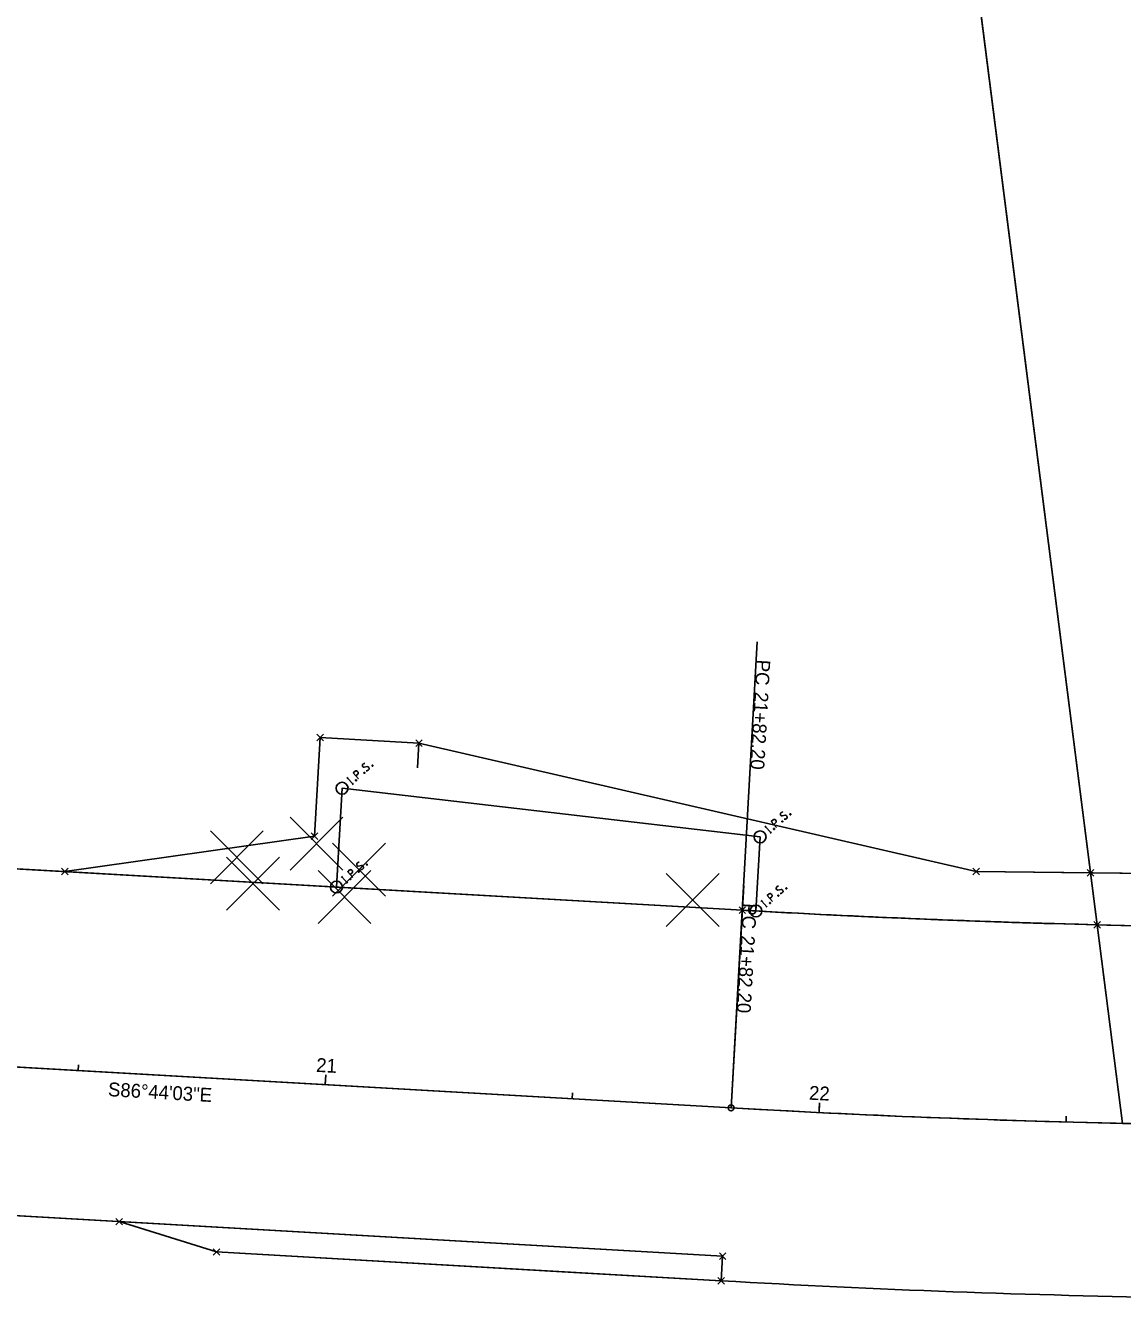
# Model space of a CAD drawing. Extents: x 2273111 to 2279616, y 652916 to 655718.
# Drawn here: x 2274544.8 to 2274766.6, y 654661.8 to 654919.2 of the extents above; entities that cross this region are included whole.
import ezdxf

# ---------------------------------------------------------------- set-up
doc = ezdxf.new("R2010")
doc.units = 0
for name, color, linetype in [('DV_X_Property_Line', 7, 'Continuous'), ('RW_P_Easement_Area', 7, 'Continuous'), ('RW_P_Esmt_SH', 7, 'Continuous'), ('RW_P_Esmt_TMP', 7, 'Continuous'), ('RW_P_Taking_Area', 7, 'Continuous'), ('RW_X_CL', 7, 'Continuous'), ('RW_X_CL_1000_Curve_Data', 7, 'Continuous'), ('RW_X_CL_1000_Stations', 7, 'Continuous'), ('RW_X_CL_100_Curve_Data', 7, 'Continuous'), ('RW_X_CL_100_Stations', 7, 'Continuous'), ('RW_X_CL_500_Stations', 7, 'Continuous'), ('RW_X_Esmt_SH', 7, 'Continuous'), ('SC_Scratch2', 7, 'Continuous'), ('SC_Scratch3', 7, 'Continuous'), ('SC_Scratch4', 7, 'Continuous'), ('SC_Scratch5', 7, 'Continuous'), ('SV_P_Control_Cells_Set', 7, 'Continuous'), ('SV_P_Mon_Cells_Set', 7, 'Continuous'), ('VG_P_Cells', 7, 'Continuous')]:
    doc.layers.add(name, color=color, linetype=linetype)

msp = doc.modelspace()

# ---------------------------------------------------------------- linework, layer by layer
at = {"layer": 'DV_X_Property_Line'}
msp.add_line((2274766.64, 654697.37), (2274705.29, 655177.83), dxfattribs=at)
at = {"layer": 'RW_P_Easement_Area'}
for p, q in [((2274603.77, 654774.71), (2274605.1, 654776.04)), ((2274603.77, 654776.04), (2274605.1, 654774.71)), ((2274603.3, 654755.41), (2274604.43, 654775.37)), ((2274604.43, 654775.37), (2274624.4, 654774.23)), ((2274623.74, 654773.57), (2274625.07, 654774.9)), ((2274623.74, 654774.9), (2274625.07, 654773.57)), ((2274624.4, 654774.23), (2274737.06, 654748.26)), ((2274608.86, 654765.1), (2274607.72, 654745.14)), ((2274693.37, 654755.28), (2274608.86, 654765.1)), ((2274552.81, 654748.27), (2274603.3, 654755.41)), ((2274602.63, 654754.74), (2274603.96, 654756.07)), ((2274602.63, 654756.07), (2274603.96, 654754.74)), ((2274692.53, 654740.3), (2274693.37, 654755.28)), ((2274552.14, 654747.6), (2274553.47, 654748.94)), ((2274552.14, 654748.94), (2274553.47, 654747.6)), ((2274607.72, 654745.14), (2274552.81, 654748.27)), ((2274736.39, 654747.59), (2274737.73, 654748.93)), ((2274736.39, 654748.93), (2274737.73, 654747.59)), ((2274737.06, 654748.26), (2274760.17, 654748.01)), ((2274761.52, 654737.51), (2274760.17, 654748.01)), ((2274760.17, 654748.01), (2274849.53, 654747.02)), ((2274760.17, 654748.01), (2274761.52, 654737.51)), ((2274689.12, 654739.79), (2274690.45, 654741.12)), ((2274689.12, 654741.12), (2274690.45, 654739.79)), ((2274760.85, 654736.84), (2274762.18, 654738.18)), ((2274760.85, 654738.18), (2274762.18, 654736.84)), ((2274563.13, 654676.86), (2274564.46, 654678.2)), ((2274563.13, 654678.2), (2274564.46, 654676.86)), ((2274583.48, 654671.4), (2274563.8, 654677.53)), ((2274563.8, 654677.53), (2274685.8, 654670.57)), ((2274582.81, 654670.73), (2274584.14, 654672.07)), ((2274582.81, 654672.07), (2274584.14, 654670.73)), ((2274685.51, 654665.58), (2274583.48, 654671.4)), ((2274685.13, 654669.9), (2274686.46, 654671.24)), ((2274685.13, 654671.24), (2274686.46, 654669.9)), ((2274685.8, 654670.57), (2274685.51, 654665.58)), ((2274684.85, 654664.91), (2274686.18, 654666.24)), ((2274684.85, 654666.24), (2274686.18, 654664.91))]:
    msp.add_line(p, q, dxfattribs=at)
for start, end in [(266.8043, 268.56091), (268.56091, 270.80398)]:
    msp.add_arc((2274818.07, 656988.81), 2252.01, start, end, dxfattribs=at)
at = {"layer": 'RW_P_Esmt_SH'}
for p, q in [((2274607.72, 654745.14), (2274608.86, 654765.1)), ((2274608.86, 654765.1), (2274693.37, 654755.28)), ((2274693.37, 654755.28), (2274692.53, 654740.3))]:
    msp.add_line(p, q, dxfattribs=at)
at = {"layer": 'RW_P_Esmt_TMP'}
for p, q in [((2274603.3, 654755.41), (2274604.43, 654775.37)), ((2274603.3, 654755.41), (2274604.43, 654775.37)), ((2274604.43, 654775.37), (2274624.4, 654774.23)), ((2274604.43, 654775.37), (2274624.4, 654774.23)), ((2274624.4, 654774.23), (2274624.12, 654769.24)), ((2274624.4, 654774.23), (2274737.06, 654748.26)), ((2274624.4, 654774.23), (2274737.06, 654748.26)), ((2274552.81, 654748.27), (2274603.3, 654755.41)), ((2274552.81, 654748.27), (2274603.3, 654755.41)), ((2274737.06, 654748.26), (2274849.53, 654747.02)), ((2274737.06, 654748.26), (2274849.53, 654747.02)), ((2274563.8, 654677.53), (2274583.48, 654671.4)), ((2274583.48, 654671.4), (2274653.36, 654667.41)), ((2274653.36, 654667.41), (2274678.32, 654665.99)), ((2274678.32, 654665.99), (2274685.51, 654665.58))]:
    msp.add_line(p, q, dxfattribs=at)
at = {"layer": 'RW_P_Taking_Area'}
for p, q in [((2274607.72, 654745.14), (2274608.86, 654765.1)), ((2274608.86, 654765.1), (2274693.37, 654755.28)), ((2274693.37, 654755.28), (2274692.53, 654740.3)), ((2274689.78, 654740.45), (2274607.72, 654745.14))]:
    msp.add_line(p, q, dxfattribs=at)
msp.add_arc((2274818.07, 656988.81), 2252.01, 266.7343, 266.8043, dxfattribs=at)
at = {"layer": 'RW_X_CL'}
msp.add_line((2274458.12, 654713.61), (2274687.5, 654700.52), dxfattribs=at)
msp.add_arc((2274818.07, 656988.81), 2292.01, 266.73428, 271.35095, dxfattribs=at)
at = {"layer": 'RW_X_CL_1000_Stations'}
msp.add_line((2274687.5, 654700.52), (2274690.07, 654745.45), dxfattribs=at)
msp.add_circle((2274687.5, 654700.52), 0.6, dxfattribs=at)
at = {"layer": 'RW_X_CL_100_Stations'}
for p, q in [((2274687.5, 654700.52), (2274692.8, 654794.66)), ((2274555.52, 654708.05), (2274555.59, 654709.25)), ((2274605.44, 654705.2), (2274605.55, 654707.2)), ((2274655.36, 654702.35), (2274655.43, 654703.55)), ((2274705.28, 654699.57), (2274705.38, 654701.57)), ((2274755.24, 654697.66), (2274755.28, 654698.86))]:
    msp.add_line(p, q, dxfattribs=at)
msp.add_circle((2274687.5, 654700.52), 0.6, dxfattribs=at)
at = {"layer": 'RW_X_CL_500_Stations'}
for p, q in [((2274687.5, 654700.52), (2274690.07, 654745.45)), ((2274605.44, 654705.2), (2274605.51, 654706.4)), ((2274705.28, 654699.57), (2274705.34, 654700.77))]:
    msp.add_line(p, q, dxfattribs=at)
msp.add_circle((2274687.5, 654700.52), 0.6, dxfattribs=at)
at = {"layer": 'RW_X_Esmt_SH'}
for p, q in [((2274460.4, 654753.54), (2274689.78, 654740.45)), ((2274456.41, 654683.66), (2274685.8, 654670.57)), ((2274685.8, 654670.57), (2274685.51, 654665.58))]:
    msp.add_line(p, q, dxfattribs=at)
for radius in [2252.01, 2327.01]:
    msp.add_arc((2274818.07, 656988.81), radius, 266.73428, 271.35095, dxfattribs=at)
at = {"layer": 'SC_Scratch2'}
msp.add_lwpolyline([(2274689.78, 654740.45), (2274607.72, 654745.14), (2274608.86, 654765.1), (2274693.37, 654755.28), (2274692.53, 654740.3)], dxfattribs=at)
msp.add_arc((2274818.07, 656988.81), 2252.01, 266.73428, 266.8043, dxfattribs=at)
at = {"layer": 'SC_Scratch3'}
for points in [[(2274692.53, 654740.3), (2274693.37, 654755.28), (2274608.86, 654765.1), (2274607.72, 654745.14), (2274552.81, 654748.27), (2274603.3, 654755.41), (2274604.43, 654775.37), (2274624.4, 654774.23), (2274737.06, 654748.26), (2274760.18, 654748.01), (2274761.52, 654737.51)], [(2274761.52, 654737.51), (2274760.18, 654748.01), (2274849.53, 654747.02), (2274849.67, 654737.02)]]:
    msp.add_lwpolyline(points, dxfattribs=at)
msp.add_lwpolyline([(2274685.8, 654670.57), (2274685.51, 654665.58), (2274583.48, 654671.4), (2274563.8, 654677.53)], close=True, dxfattribs=at)
for start, end in [(266.8043, 268.56095), (268.56095, 270.80398)]:
    msp.add_arc((2274818.07, 656988.81), 2252.01, start, end, dxfattribs=at)
at = {"layer": 'SC_Scratch4'}
for p, q in [((2274761.52, 654737.51), (2274766.64, 654697.37)), ((2274766.64, 654697.37), (2274761.52, 654737.51)), ((2274687.5, 654700.52), (2274458.12, 654713.61))]:
    msp.add_line(p, q, dxfattribs=at)
for points in [[(2274459.83, 654743.56), (2274460.4, 654753.54), (2274689.78, 654740.45)], [(2274687.5, 654700.52), (2274458.12, 654713.61), (2274439.66, 654744.86)], [(2274456.41, 654683.66), (2274685.8, 654670.57), (2274685.51, 654665.58)]]:
    msp.add_lwpolyline(points, dxfattribs=at)
for radius, start, end in [(2252.01, 266.73428, 268.56095), (2252.01, 268.56095, 270.80398), (2292.01, 266.73428, 271.35095), (2292.01, 266.73428, 268.71423), (2292.01, 268.71423, 271.35095), (2327.01, 266.73428, 271.35095)]:
    msp.add_arc((2274818.07, 656988.81), radius, start, end, dxfattribs=at)
at = {"layer": 'SC_Scratch5'}
for points in [[(2274766.64, 654697.37), (2274705.29, 655177.83), (2274905.28, 655179.09), (2274916.62, 654698.48), (2274872.11, 654697.43)], [(2274687.5, 654700.52), (2274458.12, 654713.61), (2274339.92, 654913.73), (2274394.14, 654990.65), (2274486.83, 655028.17), (2274732.19, 654967.18), (2274766.64, 654697.37)]]:
    msp.add_lwpolyline(points, dxfattribs=at)
msp.add_arc((2274818.07, 656988.81), 2292.01, 266.73428, 268.71423, dxfattribs=at)
at = {"layer": 'SV_P_Control_Cells_Set'}
for p, q in [((2274759.51, 654747.34), (2274760.84, 654748.67)), ((2274759.51, 654748.67), (2274760.84, 654747.34))]:
    msp.add_line(p, q, dxfattribs=at)
at = {"layer": 'SV_P_Mon_Cells_Set'}
for points in [[(2274612.19, 654767.01), (2274611.13, 654768.21), (2274611.52, 654768.56), (2274611.57, 654768.59), (2274611.65, 654768.62), (2274611.69, 654768.62), (2274611.73, 654768.62), (2274611.81, 654768.61), (2274611.87, 654768.58), (2274611.96, 654768.52), (2274612.06, 654768.41), (2274612.08, 654768.36), (2274612.12, 654768.29), (2274612.14, 654768.2), (2274612.13, 654768.14), (2274612.13, 654768.1), (2274612.1, 654768.04), (2274612.04, 654767.98), (2274611.65, 654767.62)], [(2274613.45, 654770.12), (2274613.42, 654770.13), (2274613.38, 654770.13), (2274613.28, 654770.09), (2274613.17, 654770.03), (2274613.1, 654769.97), (2274613.08, 654769.95), (2274613, 654769.82), (2274612.96, 654769.68), (2274612.97, 654769.56), (2274613.02, 654769.47), (2274613.07, 654769.41), (2274613.15, 654769.35), (2274613.28, 654769.34), (2274613.98, 654769.47), (2274614.05, 654769.46), (2274614.1, 654769.44), (2274614.17, 654769.4), (2274614.22, 654769.34), (2274614.26, 654769.28), (2274614.29, 654769.24), (2274614.31, 654769.17), (2274614.33, 654769.12), (2274614.34, 654769.08), (2274614.34, 654769.03), (2274614.33, 654768.99), (2274614.32, 654768.94), (2274614.3, 654768.91), (2274614.23, 654768.83), (2274614.12, 654768.73), (2274614.03, 654768.68), (2274613.86, 654768.65), (2274613.75, 654768.65)], [(2274613.28, 654768.27), (2274613.32, 654768.3), (2274613.36, 654768.31), (2274613.42, 654768.29), (2274613.46, 654768.24), (2274613.47, 654768.18), (2274613.46, 654768.14), (2274613.42, 654768.11), (2274613.38, 654768.1), (2274613.32, 654768.12), (2274613.28, 654768.17), (2274613.27, 654768.22), (2274613.28, 654768.27)], [(2274614.91, 654769.72), (2274614.95, 654769.76), (2274614.99, 654769.76), (2274615.05, 654769.74), (2274615.09, 654769.7), (2274615.1, 654769.64), (2274615.09, 654769.6), (2274615.05, 654769.56), (2274615.01, 654769.56), (2274614.95, 654769.57), (2274614.91, 654769.62), (2274614.9, 654769.68), (2274614.91, 654769.72)], [(2274609.83, 654767.05), (2274610.09, 654767.28)], [(2274611.03, 654765.97), (2274609.96, 654767.16)], [(2274610.9, 654765.85), (2274611.16, 654766.09)], [(2274611.6, 654766.77), (2274611.64, 654766.81), (2274611.68, 654766.81), (2274611.74, 654766.79), (2274611.78, 654766.75), (2274611.79, 654766.69), (2274611.78, 654766.65), (2274611.74, 654766.61), (2274611.7, 654766.61), (2274611.64, 654766.62), (2274611.6, 654766.67), (2274611.59, 654766.73), (2274611.6, 654766.77)], [(2274697.95, 654760.3), (2274697.92, 654760.31), (2274697.88, 654760.3), (2274697.78, 654760.26), (2274697.67, 654760.2), (2274697.61, 654760.14), (2274697.58, 654760.12), (2274697.5, 654760), (2274697.46, 654759.86), (2274697.47, 654759.73), (2274697.52, 654759.64), (2274697.57, 654759.59), (2274697.66, 654759.53), (2274697.78, 654759.52), (2274698.48, 654759.64), (2274698.56, 654759.64), (2274698.61, 654759.62), (2274698.68, 654759.58), (2274698.73, 654759.52), (2274698.77, 654759.46), (2274698.79, 654759.41), (2274698.82, 654759.35), (2274698.84, 654759.3), (2274698.85, 654759.26), (2274698.85, 654759.21), (2274698.84, 654759.17), (2274698.82, 654759.12), (2274698.81, 654759.09), (2274698.74, 654759.01), (2274698.63, 654758.91), (2274698.53, 654758.86), (2274698.37, 654758.83), (2274698.25, 654758.83)], [(2274694.34, 654757.22), (2274694.6, 654757.45)], [(2274696.7, 654757.19), (2274695.64, 654758.38), (2274696.03, 654758.73), (2274696.08, 654758.76), (2274696.15, 654758.79), (2274696.2, 654758.8), (2274696.24, 654758.8), (2274696.31, 654758.78), (2274696.38, 654758.76), (2274696.46, 654758.7), (2274696.56, 654758.58), (2274696.59, 654758.54), (2274696.62, 654758.47), (2274696.65, 654758.37), (2274696.64, 654758.32), (2274696.63, 654758.27), (2274696.61, 654758.22), (2274696.55, 654758.15), (2274696.16, 654757.8)], [(2274697.78, 654758.44), (2274697.83, 654758.48), (2274697.87, 654758.48), (2274697.92, 654758.47), (2274697.97, 654758.42), (2274697.98, 654758.36), (2274697.97, 654758.32), (2274697.93, 654758.28), (2274697.89, 654758.28), (2274697.83, 654758.3), (2274697.79, 654758.34), (2274697.78, 654758.4), (2274697.78, 654758.44)], [(2274699.41, 654759.9), (2274699.45, 654759.93), (2274699.49, 654759.94), (2274699.55, 654759.92), (2274699.59, 654759.87), (2274699.6, 654759.82), (2274699.59, 654759.77), (2274699.55, 654759.74), (2274699.51, 654759.73), (2274699.45, 654759.75), (2274699.41, 654759.8), (2274699.4, 654759.86), (2274699.41, 654759.9)], [(2274695.54, 654756.14), (2274694.47, 654757.34)], [(2274695.4, 654756.03), (2274695.67, 654756.26)], [(2274696.11, 654756.94), (2274696.15, 654756.98), (2274696.19, 654756.98), (2274696.25, 654756.97), (2274696.29, 654756.92), (2274696.3, 654756.86), (2274696.29, 654756.82), (2274696.25, 654756.78), (2274696.21, 654756.78), (2274696.15, 654756.8), (2274696.11, 654756.84), (2274696.1, 654756.9), (2274696.11, 654756.94)], [(2274612.31, 654750.16), (2274612.28, 654750.16), (2274612.24, 654750.16), (2274612.14, 654750.12), (2274612.03, 654750.06), (2274611.96, 654750), (2274611.94, 654749.98), (2274611.86, 654749.85), (2274611.82, 654749.72), (2274611.83, 654749.59), (2274611.88, 654749.5), (2274611.93, 654749.44), (2274612.01, 654749.38), (2274612.14, 654749.38), (2274612.84, 654749.5), (2274612.92, 654749.5), (2274612.97, 654749.47), (2274613.03, 654749.43), (2274613.08, 654749.38), (2274613.12, 654749.31), (2274613.15, 654749.27), (2274613.18, 654749.21), (2274613.19, 654749.15), (2274613.2, 654749.11), (2274613.2, 654749.06), (2274613.19, 654749.02), (2274613.18, 654748.97), (2274613.16, 654748.94), (2274613.1, 654748.86), (2274612.98, 654748.76), (2274612.89, 654748.71), (2274612.72, 654748.69), (2274612.61, 654748.68)], [(2274613.77, 654749.75), (2274613.81, 654749.79), (2274613.85, 654749.79), (2274613.91, 654749.78), (2274613.95, 654749.73), (2274613.96, 654749.67), (2274613.95, 654749.63), (2274613.91, 654749.59), (2274613.87, 654749.59), (2274613.81, 654749.6), (2274613.77, 654749.65), (2274613.76, 654749.71), (2274613.77, 654749.75)], [(2274608.69, 654747.08), (2274608.95, 654747.31)], [(2274609.89, 654746), (2274608.82, 654747.2)], [(2274611.06, 654747.04), (2274609.99, 654748.24), (2274610.39, 654748.59), (2274610.43, 654748.62), (2274610.51, 654748.65), (2274610.55, 654748.65), (2274610.59, 654748.66), (2274610.67, 654748.64), (2274610.73, 654748.61), (2274610.82, 654748.55), (2274610.92, 654748.44), (2274610.94, 654748.4), (2274610.98, 654748.33), (2274611, 654748.23), (2274610.99, 654748.17), (2274610.99, 654748.13), (2274610.96, 654748.08), (2274610.91, 654748.01), (2274610.51, 654747.66)], [(2274612.14, 654748.3), (2274612.18, 654748.33), (2274612.22, 654748.34), (2274612.28, 654748.32), (2274612.32, 654748.28), (2274612.33, 654748.22), (2274612.32, 654748.17), (2274612.28, 654748.14), (2274612.24, 654748.14), (2274612.18, 654748.15), (2274612.14, 654748.2), (2274612.13, 654748.26), (2274612.14, 654748.3)], [(2274609.76, 654745.89), (2274610.02, 654746.12)], [(2274610.46, 654746.8), (2274610.5, 654746.84), (2274610.54, 654746.84), (2274610.6, 654746.83), (2274610.64, 654746.78), (2274610.65, 654746.72), (2274610.64, 654746.68), (2274610.6, 654746.64), (2274610.56, 654746.64), (2274610.5, 654746.65), (2274610.46, 654746.7), (2274610.45, 654746.76), (2274610.46, 654746.8)], [(2274697.12, 654745.33), (2274697.09, 654745.33), (2274697.04, 654745.33), (2274696.94, 654745.29), (2274696.84, 654745.23), (2274696.77, 654745.17), (2274696.75, 654745.15), (2274696.67, 654745.02), (2274696.63, 654744.88), (2274696.64, 654744.76), (2274696.69, 654744.67), (2274696.74, 654744.61), (2274696.82, 654744.55), (2274696.94, 654744.54), (2274697.65, 654744.67), (2274697.72, 654744.67), (2274697.77, 654744.64), (2274697.84, 654744.6), (2274697.89, 654744.55), (2274697.93, 654744.48), (2274697.96, 654744.44), (2274697.98, 654744.37), (2274698, 654744.32), (2274698.01, 654744.28), (2274698.01, 654744.23), (2274698, 654744.19), (2274697.99, 654744.14), (2274697.97, 654744.11), (2274697.9, 654744.03), (2274697.79, 654743.93), (2274697.7, 654743.88), (2274697.53, 654743.85), (2274697.42, 654743.85)], [(2274698.57, 654744.92), (2274698.62, 654744.96), (2274698.66, 654744.96), (2274698.72, 654744.95), (2274698.76, 654744.9), (2274698.77, 654744.84), (2274698.76, 654744.8), (2274698.72, 654744.76), (2274698.68, 654744.76), (2274698.62, 654744.77), (2274698.58, 654744.82), (2274698.57, 654744.88), (2274698.57, 654744.92)], [(2274693.5, 654742.24), (2274693.76, 654742.48)], [(2274694.7, 654741.17), (2274693.63, 654742.36)], [(2274695.87, 654742.21), (2274694.8, 654743.4), (2274695.19, 654743.76), (2274695.24, 654743.78), (2274695.32, 654743.82), (2274695.36, 654743.82), (2274695.4, 654743.82), (2274695.48, 654743.81), (2274695.54, 654743.78), (2274695.63, 654743.72), (2274695.73, 654743.61), (2274695.75, 654743.56), (2274695.79, 654743.49), (2274695.81, 654743.4), (2274695.8, 654743.34), (2274695.8, 654743.3), (2274695.77, 654743.24), (2274695.71, 654743.17), (2274695.32, 654742.82)], [(2274695.27, 654741.97), (2274695.31, 654742), (2274695.35, 654742.01), (2274695.41, 654741.99), (2274695.45, 654741.94), (2274695.46, 654741.88), (2274695.46, 654741.84), (2274695.41, 654741.81), (2274695.37, 654741.8), (2274695.31, 654741.82), (2274695.27, 654741.87), (2274695.26, 654741.93), (2274695.27, 654741.97)], [(2274696.95, 654743.47), (2274696.99, 654743.5), (2274697.03, 654743.51), (2274697.09, 654743.49), (2274697.13, 654743.44), (2274697.14, 654743.38), (2274697.13, 654743.34), (2274697.09, 654743.31), (2274697.05, 654743.3), (2274696.99, 654743.32), (2274696.95, 654743.37), (2274696.94, 654743.42), (2274696.95, 654743.47)], [(2274694.57, 654741.05), (2274694.83, 654741.29)]]:
    msp.add_lwpolyline(points, dxfattribs=at)
for centre in [(2274608.86, 654765.1), (2274693.37, 654755.28), (2274607.72, 654745.14), (2274692.53, 654740.3)]:
    msp.add_circle(centre, 1.2, dxfattribs=at)
at = {"layer": 'VG_P_Cells'}
for p, q in [((2274598.34, 654759.23), (2274609.03, 654748.54)), ((2274609.03, 654759.23), (2274598.34, 654748.54)), ((2274582.24, 654756.5), (2274592.93, 654745.81)), ((2274592.93, 654756.5), (2274582.24, 654745.81)), ((2274603.68, 654753.88), (2274603.68, 654753.88)), ((2274606.95, 654753.99), (2274617.64, 654743.3)), ((2274617.64, 654753.99), (2274606.95, 654743.3)), ((2274585.5, 654751.15), (2274596.19, 654740.46)), ((2274596.19, 654751.15), (2274585.5, 654740.46)), ((2274587.58, 654751.16), (2274587.58, 654751.16)), ((2274603.99, 654748.46), (2274614.68, 654737.77)), ((2274614.68, 654748.46), (2274603.99, 654737.77)), ((2274612.3, 654748.64), (2274612.3, 654748.64)), ((2274674.38, 654747.89), (2274685.07, 654737.2)), ((2274685.07, 654747.89), (2274674.38, 654737.2)), ((2274590.84, 654745.81), (2274590.84, 654745.81)), ((2274609.34, 654743.11), (2274609.34, 654743.11)), ((2274679.73, 654742.55), (2274679.73, 654742.55))]:
    msp.add_line(p, q, dxfattribs=at)

# ---------------------------------------------------------------- texts
at = {"layer": 'RW_X_CL_1000_Curve_Data'}
msp.add_text('S86°44\'03"E', height=2.8, rotation=356.7343, dxfattribs=at).set_placement((2274561.48, 654702.9))
at = {"layer": 'RW_X_CL_1000_Stations'}
for s, p in [('PC', (2274689.92, 654741.94)), ('21+82.20', (2274689.54, 654735.43))]:
    msp.add_text(s, height=2.8, rotation=266.7343, dxfattribs=at).set_placement(p)
at = {"layer": 'RW_X_CL_100_Curve_Data'}
msp.add_text('S86°44\'03"E', height=2.8, rotation=356.7343, dxfattribs=at).set_placement((2274561.48, 654702.9))
msp.add_text('S86°44\'03"E', height=2.8, rotation=356.7343, dxfattribs=at).set_placement((2274561.48, 654702.9))
at = {"layer": 'RW_X_CL_100_Stations'}
for s, rotation, p in [('PC', 266.7343, (2274692.65, 654791.15)), ('21+82.20', 266.7343, (2274692.28, 654784.64)), ('21', 356.7343, (2274603.56, 654707.81)), ('22', 357.1793, (2274703.22, 654702.18))]:
    msp.add_text(s, height=2.8, rotation=rotation, dxfattribs=at).set_placement(p)
at = {"layer": 'RW_X_CL_500_Stations'}
for s, p in [('PC', (2274689.92, 654741.94)), ('21+82.20', (2274689.54, 654735.43))]:
    msp.add_text(s, height=2.8, rotation=266.7343, dxfattribs=at).set_placement(p)

doc.saveas('drawing.dxf')
